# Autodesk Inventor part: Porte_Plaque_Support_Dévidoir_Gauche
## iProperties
Created: 2009-01
Part Number: Porte_Plaque_Support_Dévidoir_Gauche
Document SubType Name: Sheet Metal
Designer: claivier
Author: claivier
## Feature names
1. Extrusion1
2. Corps dérivé1 [Tagging]
